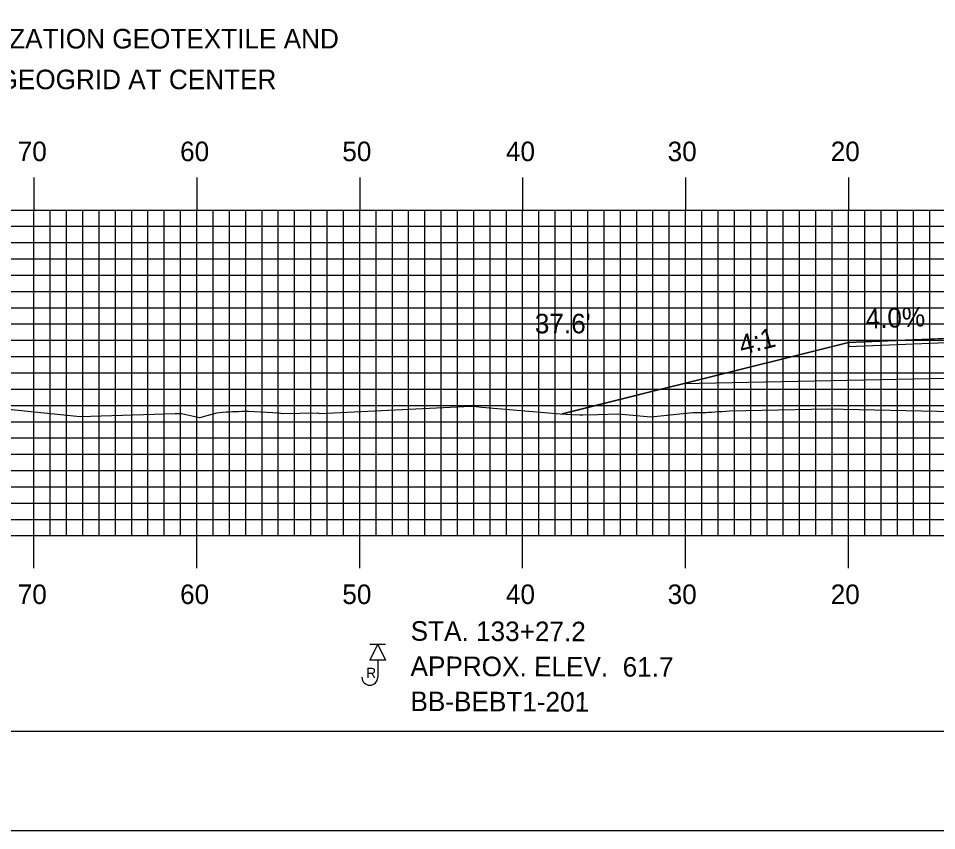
# Model space of a CAD drawing. Extents: x 1774777 to 1775120, y 442591 to 442811.
# Drawn here: x 1774871.7 to 1774928.1, y 442590.5 to 442640.4 of the extents above; entities that cross this region are included whole.
import ezdxf

# ---------------------------------------------------------------- set-up
doc = ezdxf.new("R2010")
doc.units = 0
for name, color, linetype in [('ANNOTATION', 7, 'Continuous'), ('BORDER', 7, 'Continuous'), ('BORING - REFUSAL', 7, 'Continuous'), ('D_Roadway_Centerline', 7, 'Continuous'), ('D_Roadway_Edge_Shoulder', 7, 'Continuous'), ('D_Roadway_SlopeLines', 7, 'Continuous'), ('D_Roadway_SubGrade', 7, 'Continuous'), ('D_Text_Standard', 7, 'Continuous'), ('H_V ANNOTATION', 7, 'Continuous'), ('MAJOR', 7, 'Continuous'), ('MINOR', 7, 'Continuous'), ('PLOT BOUNDARY', 7, 'Continuous'), ('S_Roadway_Centerline', 7, 'Continuous')]:
    doc.layers.add(name, color=color, linetype=linetype)

msp = doc.modelspace()

# ---------------------------------------------------------------- linework, layer by layer
at = {"layer": 'BORDER'}
msp.add_lwpolyline([(1774793.085, 442596.665), (1775113.085, 442596.665), (1775113.085, 442806.665), (1774793.085, 442806.665)], close=True, dxfattribs=at)
at = {"layer": 'BORING - REFUSAL'}
for p, q in [((1774894.265, 442601.986), (1774893.305, 442601.986)), ((1774893.785, 442601.026), (1774893.785, 442599.967))]:
    msp.add_line(p, q, dxfattribs=at)
msp.add_lwpolyline([(1774893.785, 442601.986), (1774894.265, 442601.026), (1774893.305, 442601.026)], close=True, dxfattribs=at)
msp.add_arc((1774893.3, 442599.967), 0.485, 180, 0, dxfattribs=at)
at = {"layer": 'D_Roadway_Centerline'}
msp.add_lwpolyline([(1774905.121, 442616.142), (1774909.311, 442617.19), (1774910.685, 442617.534), (1774911.346, 442617.699), (1774912.511, 442617.99), (1774915.522, 442618.743), (1774922.685, 442620.534), (1774928.925, 442620.784), (1774930.685, 442620.854), (1774935.129, 442620.943), (1774942.685, 442621.094), (1774951.841, 442620.911), (1774954.686, 442620.854), (1774962.686, 442620.534), (1774972.859, 442617.99), (1774973.54, 442617.82)], dxfattribs=at)
at = {"layer": 'D_Roadway_Edge_Shoulder'}
msp.add_lwpolyline([(1774930.685, 442620.854), (1774922.685, 442620.534), (1774922.685, 442620.284), (1774930.685, 442620.604)], close=True, dxfattribs=at)
at = {"layer": 'D_Roadway_SlopeLines'}
msp.add_lwpolyline([(1774922.685, 442620.534), (1774912.511, 442617.99), (1774910.685, 442617.534), (1774905.12, 442616.142)], dxfattribs=at)
at = {"layer": 'D_Roadway_SubGrade'}
msp.add_lwpolyline([(1774930.685, 442618.354), (1774912.511, 442617.99), (1774922.685, 442620.534), (1774922.685, 442620.284), (1774930.685, 442620.604), (1774942.685, 442620.844), (1774954.686, 442620.604), (1774962.686, 442620.284), (1774962.686, 442620.534), (1774972.859, 442617.99), (1774954.686, 442618.354), (1774942.685, 442618.594)], close=True, dxfattribs=at)
at = {"layer": 'MAJOR'}
for p, q in [((1774872.685, 442630.669), (1774872.685, 442628.665)), ((1774882.685, 442630.669), (1774882.685, 442628.665)), ((1774892.685, 442630.669), (1774892.685, 442628.665)), ((1774902.685, 442630.669), (1774902.685, 442628.665)), ((1774912.685, 442630.669), (1774912.685, 442628.665)), ((1774922.685, 442630.669), (1774922.685, 442628.665)), ((1774802.685, 442628.665), (1775082.685, 442628.665)), ((1774802.685, 442628.665), (1775082.685, 442628.665)), ((1774872.685, 442608.665), (1774872.685, 442628.665)), ((1774882.685, 442608.665), (1774882.685, 442628.665)), ((1774892.685, 442608.665), (1774892.685, 442628.665)), ((1774902.685, 442608.665), (1774902.685, 442628.665)), ((1774912.685, 442608.665), (1774912.685, 442628.665)), ((1774922.685, 442608.665), (1774922.685, 442628.665)), ((1774802.685, 442623.665), (1775082.685, 442623.665)), ((1774802.685, 442618.665), (1775082.685, 442618.665)), ((1774802.685, 442613.665), (1775082.685, 442613.665)), ((1774802.685, 442608.665), (1775082.685, 442608.665)), ((1774802.685, 442608.665), (1775082.685, 442608.665)), ((1774872.685, 442606.661), (1774872.685, 442608.665)), ((1774882.685, 442606.661), (1774882.685, 442608.665)), ((1774892.685, 442606.661), (1774892.685, 442608.665)), ((1774902.685, 442606.661), (1774902.685, 442608.665)), ((1774912.685, 442606.661), (1774912.685, 442608.665)), ((1774922.685, 442606.661), (1774922.685, 442608.665))]:
    msp.add_line(p, q, dxfattribs=at)
at = {"layer": 'MINOR'}
for p, q in [((1774873.685, 442608.665), (1774873.685, 442628.665)), ((1774874.685, 442608.665), (1774874.685, 442628.665)), ((1774875.685, 442608.665), (1774875.685, 442628.665)), ((1774876.685, 442608.665), (1774876.685, 442628.665)), ((1774877.685, 442608.665), (1774877.685, 442628.665)), ((1774878.685, 442608.665), (1774878.685, 442628.665)), ((1774879.685, 442608.665), (1774879.685, 442628.665)), ((1774880.685, 442608.665), (1774880.685, 442628.665)), ((1774881.685, 442608.665), (1774881.685, 442628.665)), ((1774883.685, 442608.665), (1774883.685, 442628.665)), ((1774884.685, 442608.665), (1774884.685, 442628.665)), ((1774885.685, 442608.665), (1774885.685, 442628.665)), ((1774886.685, 442608.665), (1774886.685, 442628.665)), ((1774887.685, 442608.665), (1774887.685, 442628.665)), ((1774888.685, 442608.665), (1774888.685, 442628.665)), ((1774889.685, 442608.665), (1774889.685, 442628.665)), ((1774890.685, 442608.665), (1774890.685, 442628.665)), ((1774891.685, 442608.665), (1774891.685, 442628.665)), ((1774893.685, 442608.665), (1774893.685, 442628.665)), ((1774894.685, 442608.665), (1774894.685, 442628.665)), ((1774895.685, 442608.665), (1774895.685, 442628.665)), ((1774896.685, 442608.665), (1774896.685, 442628.665)), ((1774897.685, 442608.665), (1774897.685, 442628.665)), ((1774898.685, 442608.665), (1774898.685, 442628.665)), ((1774899.685, 442608.665), (1774899.685, 442628.665)), ((1774900.685, 442608.665), (1774900.685, 442628.665)), ((1774901.685, 442608.665), (1774901.685, 442628.665)), ((1774903.685, 442608.665), (1774903.685, 442628.665)), ((1774904.685, 442608.665), (1774904.685, 442628.665)), ((1774905.685, 442608.665), (1774905.685, 442628.665)), ((1774906.685, 442608.665), (1774906.685, 442628.665)), ((1774907.685, 442608.665), (1774907.685, 442628.665)), ((1774908.685, 442608.665), (1774908.685, 442628.665)), ((1774909.685, 442608.665), (1774909.685, 442628.665)), ((1774910.685, 442608.665), (1774910.685, 442628.665)), ((1774911.685, 442608.665), (1774911.685, 442628.665)), ((1774913.685, 442608.665), (1774913.685, 442628.665)), ((1774914.685, 442608.665), (1774914.685, 442628.665)), ((1774915.685, 442608.665), (1774915.685, 442628.665)), ((1774916.685, 442608.665), (1774916.685, 442628.665)), ((1774917.685, 442608.665), (1774917.685, 442628.665)), ((1774918.685, 442608.665), (1774918.685, 442628.665)), ((1774919.685, 442608.665), (1774919.685, 442628.665)), ((1774920.685, 442608.665), (1774920.685, 442628.665)), ((1774921.685, 442608.665), (1774921.685, 442628.665)), ((1774923.685, 442608.665), (1774923.685, 442628.665)), ((1774924.685, 442608.665), (1774924.685, 442628.665)), ((1774925.685, 442608.665), (1774925.685, 442628.665)), ((1774926.685, 442608.665), (1774926.685, 442628.665)), ((1774927.685, 442608.665), (1774927.685, 442628.665)), ((1774802.685, 442627.665), (1775082.685, 442627.665)), ((1774802.685, 442626.665), (1775082.685, 442626.665)), ((1774802.685, 442625.665), (1775082.685, 442625.665)), ((1774802.685, 442624.665), (1775082.685, 442624.665)), ((1774802.685, 442622.665), (1775082.685, 442622.665)), ((1774802.685, 442621.665), (1775082.685, 442621.665)), ((1774802.685, 442620.665), (1775082.685, 442620.665)), ((1774802.685, 442619.665), (1775082.685, 442619.665)), ((1774802.685, 442617.665), (1775082.685, 442617.665)), ((1774802.685, 442616.665), (1775082.685, 442616.665)), ((1774802.685, 442615.665), (1775082.685, 442615.665)), ((1774802.685, 442614.665), (1775082.685, 442614.665)), ((1774802.685, 442612.665), (1775082.685, 442612.665)), ((1774802.685, 442611.665), (1775082.685, 442611.665)), ((1774802.685, 442610.665), (1775082.685, 442610.665)), ((1774802.685, 442609.665), (1775082.685, 442609.665))]:
    msp.add_line(p, q, dxfattribs=at)
at = {"layer": 'PLOT BOUNDARY'}
msp.add_lwpolyline([(1774776.898, 442590.547), (1775116.898, 442590.547), (1775116.898, 442810.547), (1774776.898, 442810.547)], close=True, dxfattribs=at)
at = {"layer": 'S_Roadway_Centerline'}
msp.add_lwpolyline([(1774866.468, 442616.902), (1774875.527, 442615.987), (1774881.344, 442616.161), (1774881.573, 442616.166), (1774881.75, 442616.17), (1774882.854, 442615.913), (1774882.898, 442615.926), (1774882.959, 442615.944), (1774883.041, 442615.968), (1774883.156, 442616), (1774883.317, 442616.044), (1774883.553, 442616.106), (1774883.919, 442616.201), (1774884.067, 442616.238), (1774884.248, 442616.251), (1774884.488, 442616.265), (1774884.705, 442616.277), (1774884.873, 442616.285), (1774885.055, 442616.292), (1774885.247, 442616.3), (1774885.447, 442616.307), (1774885.649, 442616.313), (1774885.85, 442616.318), (1774887.719, 442616.206), (1774887.834, 442616.184), (1774887.938, 442616.16), (1774890.084, 442616.203), (1774890.224, 442616.176), (1774899.513, 442616.617), (1774899.832, 442616.592), (1774900.176, 442616.561), (1774904.977, 442616.15), (1774905.353, 442616.131), (1774905.69, 442616.115), (1774906.193, 442616.091), (1774906.384, 442616.082), (1774907.305, 442616.106), (1774908.554, 442616.137), (1774910.559, 442615.957), (1774913.131, 442616.225), (1774913.354, 442616.226), (1774913.568, 442616.229), (1774913.768, 442616.232), (1774913.945, 442616.236), (1774914.095, 442616.242), (1774914.273, 442616.253), (1774914.479, 442616.266), (1774914.701, 442616.282), (1774914.931, 442616.3), (1774915.161, 442616.319), (1774915.385, 442616.338), (1774921.409, 442616.446), (1774929.081, 442616.283)], dxfattribs=at)

# ---------------------------------------------------------------- texts
at = {"layer": 'ANNOTATION'}
for s, rotation, p in [('4.0%', 2.2907, (1774923.757, 442621.379)), ('4:1', 14.0391, (1774916.134, 442619.758))]:
    msp.add_text(s, height=1.2, rotation=rotation, dxfattribs=at).set_placement(p)
at = {"layer": 'BORING - REFUSAL'}
for s, p in [('STA. 133+27.2', (1774895.808, 442602.211)), ('APPROX. ELEV.  61.7', (1774895.801, 442600.051)), ('BB-BEBT1-201', (1774895.794, 442597.891))]:
    msp.add_text(s, height=1.2, rotation=359.8142, dxfattribs=at).set_placement(p)
msp.add_text('R', height=0.64, dxfattribs=at).set_placement((1774893.076, 442599.912))
at = {"layer": 'D_Text_Standard'}
for s, p in [('WRAPPED WITH STABALIZATION GEOTEXTILE AND', (1774851.46, 442638.586)), ('WITH REINFORCEMENT GEOGRID AT CENTER', (1774851.46, 442636.086)), ("37.6'", (1774903.432, 442621.091))]:
    msp.add_text(s, height=1.2, dxfattribs=at).set_placement(p)
at = {"layer": 'H_V ANNOTATION'}
for s, p in [('70', (1774871.689, 442631.665)), ('60', (1774881.657, 442631.665)), ('50', (1774891.614, 442631.665)), ('40', (1774901.657, 442631.665)), ('30', (1774911.583, 442631.665)), ('20', (1774921.593, 442631.665)), ('70', (1774871.689, 442604.465)), ('60', (1774881.657, 442604.465)), ('50', (1774891.614, 442604.465)), ('40', (1774901.657, 442604.465)), ('30', (1774911.583, 442604.465)), ('20', (1774921.593, 442604.465))]:
    msp.add_text(s, height=1.2, dxfattribs=at).set_placement(p)

doc.saveas('drawing.dxf')
